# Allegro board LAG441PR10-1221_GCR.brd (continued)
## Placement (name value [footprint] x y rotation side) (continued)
CV17  0.1U_0201_10V6K  [C_0201]  43 73.42 90 top
CV18  0.1U_0201_10V6K  [C_0201]  43.57 73.42 90 top
CV19  680P_0201_50V7K  [C_0201]  34.48 75.7 0 top
CV20  0.1U_0201_10V6K  [C_0201]  36.64 76.5 180 top
CV21  10U_0402_6.3V6M  [C_0402]  37.38 74.5 180 top
CV22  22P_0201_25V8  [C_0201]  37.45 75.27 180 top
CV23  100P_0201_50V8J  [C_0201]  36.64 75.93 180 top
CV24  10U_0603_25V6M  [C_0603]  33.43 76.1 180 top
CV25  0.1U_0402_25V6  [C_0402]  33.5 77.16 180 top
CV26  0.1U_0201_10V6K  [C_0201]  60.96 62.31 0 bottom
CV27  0.1U_0201_6.3V6K  [C_0201]  304.58 4.65 180 top
CV31  10U_0402_6.3V6M  [C_0402]  47.59 57.98 90 top
CV32  0.1U_0201_10V6K  [C_0201]  46.27 58.15 90 top
CV33  0.1U_0201_10V6K  [C_0201]  45.63 58.15 90 top
CV34  68P_0201_25V8  [C_0201]  46.85 58.15 90 top
CV37  0.1U_0201_25V6K  [C_0201]  50.52 64.75 90 top
CV38  2200P_0402_50V7K  [C_0402]  52.08 64.23 90 top
CV39  0.1U_0201_10V6K  [C_0201]  70.64 61.93 0 top
CV40  0.1U_0201_25V6K  [C_0201]  60.49 62.76 0 top
CV41  2200P_0402_50V7K  [C_0402]  61.25 63.52 90 top
CV42  0.1U_0201_10V6K  [C_0201]  246.9 37.1 180 top
CV43  0.1U_0201_10V6K  [C_0201]  246.9 37.74 180 top
CV44  0.1U_0201_10V6K  [C_0201]  38.07 75.96 0 top
CV45  15P_0201_50V8J  [C_0201]  38.07 76.54 0 top
CV50  0.1U_0201_10V6K  [C_0201]  54.43 61.49 180 bottom
CV51  0.1U_0201_10V6K  [C_0201]  54.24 58.06 180 bottom
CV52  1U_0201_6.3V6M  [C_0201]  54.24 58.69 180 bottom
CV53  0.1U_0201_10V6K  [C_0201]  54.24 59.33 180 bottom
CV55  0.1U_0201_10V6K  [C_0201]  43.71 71.21 0 top
CV56  0.1U_0201_10V6K  [C_0201]  36.44 77.59 180 top
CZ1  0.1U_0201_10V6K  [C_0201]  96.9 59.45 0 bottom
CZ2  1U_0201_6.3V6M  [C_0201]  97.95 61.91 270 bottom
CZ3  1U_0201_6.3V6M  [C_0201]  80.17 63.8 0 bottom
CZ5  0.1U_0201_10V6K  [C_0201]  78.33 61.42 270 bottom
CZ6  0.1U_0201_10V6K  [C_0201]  98.53 19.07 0 bottom
CZ7  1U_0201_6.3V6M  [C_0201]  99.1 18.5 180 bottom
CZ15  0.1U_0201_10V6K  [C_0201]  43.56 29.36 0 top
CZ16  10U_0402_6.3V6M  [C_0402]  43.39 28.59 0 top
CZ17  10U_0402_6.3V6M  [C_0402]  47.08 28.59 0 top
CZ18  0.1U_0201_10V6K  [C_0201]  47.18 29.36 0 top
CZ19  0.1U_0201_10V6K  [C_0201]  44.26 36.87 90 top
CZ20  0.1U_0201_10V6K  [C_0201]  43.69 36.85 90 top
CZ21  10U_0402_6.3V6M  [C_0402]  42.9 36.98 90 top
CZ22  12P_0201_50V8J  [C_0201]  41.57 29.95 90 top
CZ23  68P_0201_50V8J  [C_0201]  41.59 29.36 0 top
CZ28  0.1U_0201_10V6K  [C_0201]  45.72 38.25 0 top
D3  -  [L05ESDL5V0NA-4_SLP2510P8-10-9]  308.09 65.88 180 top
D9  -  [BAT54LPS-7_X2-DFN1006-2-2]  201.81 33.04 0 bottom
D203  -  [RB751S40T1G_SOD523-2]  103.15 12.24 90 top
D481  -  [RB751V40_SC76-2]  146.72 21.38 180 bottom
DA1  AZ5125-01H.R7G_SOD523-2  [AZ5125-01HPR7G_SOD523-2]  292.85 28.97 0 top
DA4  AZ5123-01F.R7G_DFN1006P2X2  [AZ5123-01FPR7G_DFN1006P2X2]  298.42 14.75 0 top
DA5  AZ5123-01F.R7G_DFN1006P2X2  [AZ5123-01FPR7G_DFN1006P2X2]  295.76 26.43 270 top
DA8  AZ5123-01F.R7G_DFN1006P2X2  [AZ5123-01FPR7G_DFN1006P2X2]  306.68 25.55 270 top
DA9  AZ5123-01F.R7G_DFN1006P2X2  [AZ5123-01FPR7G_DFN1006P2X2]  304.52 25.55 270 top
DA10  -  [ESD203-B1-02EL_TSLP-2-20-2]  295.24 14.68 180 top
DA11  -  [ESD203-B1-02EL_TSLP-2-20-2]  296.62 14.68 0 top
DA12  -  [ESD203-B1-02EL_TSLP-2-20-2]  293.07 14.68 0 top
DA13  -  [ESD203-B1-02EL_TSLP-2-20-2]  291.68 14.68 180 top
DA25  AZ5123-01F.R7G_DFN1006P2X2  [AZ5123-01FPR7G_DFN1006P2X2]  299.19 16.53 180 top
DA26  AZ5123-01F.R7G_DFN1006P2X2  [AZ5123-01FPR7G_DFN1006P2X2]  299.29 13.23 180 top
DA27  -  [RB751S-40_SOD523-2]  275.67 27.64 0 top
DB3  -  [BAT54HT1G_SOD323-2]  308.2 5.67 90 top
DB4  -  [BAT54HT1G_SOD323-2]  102.7 25.01 270 top
DB5  -  [RB751S-40_SOD523-2]  313.12 2.69 180 top
DB9  -  [RB751S-40_SOD523-2]  272.26 14.43 90 top
DC1  RB751540_SOD523  [RB520SM-30T2R_EMD2-2]  128.6 31.96 0 bottom
DC2  RB751540_SOD523  [RB520SM-30T2R_EMD2-2]  118.59 30.15 270 bottom
DC5  -  [RB751S-40_SOD523-2]  110.63 59.9 0 bottom
DC6  -  [RB751S-40_SOD523-2]  110.66 61.17 0 bottom
DC7  -  [RB751S-40_SOD523-2]  123.79 31.97 90 bottom
DC8  -  [RB751S-40_SOD523-2]  37.48 77.64 0 top
DE4  -  [AZ5B25-01F_DFN0603P2Y2]  291.18 74.07 90 bottom
DE6  -  [RB751V40_SC76-2]  202.16 30.5 270 bottom
DE7  -  [RB751S-40_SOD523-2]  271.45 46.57 270 top
DE8  -  [RB751S-40_SOD523-2]  277.21 60.92 0 top
DI7  -  [AZ5B25-01F_DFN0603P2Y2]  299.44 57.64 90 top
DI8  -  [AZ5B25-01F_DFN0603P2Y2]  299.44 56.95 270 top
DI9  -  [L05ESDL5V0NA-4_SLP2510P8-10-9]  298.37 55.5 90 top
DI13  -  [AZ5B25-01F_DFN0603P2Y2]  15.04 9.6 90 bottom
DI14  -  [AZ5B25-01F_DFN0603P2Y2]  15.04 8.85 270 bottom
DI15  PESD5V0H1BSF_SOD962-2-2  [ESD101-B1-02ELS_TSSLP-2-4-2]  15.04 5.92 270 bottom
DI16  PESD5V0H1BSF_SOD962-2-2  [ESD101-B1-02ELS_TSSLP-2-4-2]  15.04 11.89 270 bottom
DI17  PESD5V0H1BSF_SOD962-2-2  [ESD101-B1-02ELS_TSSLP-2-4-2]  15.04 6.56 90 bottom
DI18  PESD5V0H1BSF_SOD962-2-2  [ESD101-B1-02ELS_TSSLP-2-4-2]  15.04 12.53 90 bottom
DM1  PESD5V0H1BSF_SOD962-2-2  [ESD101-B1-02ELS_TSSLP-2-4-2]  14.83 27.01 90 top
DM2  PESD5V0H1BSF_SOD962-2-2  [ESD101-B1-02ELS_TSSLP-2-4-2]  14.83 29.55 90 top
DM3  PESD5V0H1BSF_SOD962-2-2  [ESD101-B1-02ELS_TSSLP-2-4-2]  14.83 36.71 90 top
DM4  PESD5V0H1BSF_SOD962-2-2  [ESD101-B1-02ELS_TSSLP-2-4-2]  14.83 32.59 90 top
DM5  PESD5V0H1BSF_SOD962-2-2  [ESD101-B1-02ELS_TSSLP-2-4-2]  14.83 31.96 270 top
DM6  PESD5V0H1BSF_SOD962-2-2  [ESD101-B1-02ELS_TSSLP-2-4-2]  14.83 26.37 270 top
DM7  PESD5V0H1BSF_SOD962-2-2  [ESD101-B1-02ELS_TSSLP-2-4-2]  14.83 28.91 270 top
DM8  PESD5V0H1BSF_SOD962-2-2  [ESD101-B1-02ELS_TSSLP-2-4-2]  14.83 36.09 270 top
DN7  -  [BAT54CW_SOT323-3]  252.45 42.25 180 top
DP1  -  [AZ5B25-01F_DFN0603P2Y2]  194.92 19.2 180 bottom
DP2  -  [AZ5B25-01F_DFN0603P2Y2]  195.68 19.2 0 bottom
DP3  -  [AZ5B25-01F_DFN0603P2Y2]  193.39 19.2 0 bottom
DP4  -  [AZ5B25-01F_DFN0603P2Y2]  192.63 19.2 180 bottom
DS1  -  [L05ESDL5V0NA-4_SLP2510P8-10-9]  292.72 31.15 270 bottom
DS2  -  [PESD5V0U2BT_SOT23-3]  290.68 40.56 0 bottom
DT4  PESD5V0H1BSF_SOD962-2-2  [ESD101-B1-02ELS_TSSLP-2-4-2]  9.3 71.7 90 top
DT6  PESD5V0H1BSF_SOD962-2-2  [ESD101-B1-02ELS_TSSLP-2-4-2]  9.3 56.48 90 top
DT7  PESD5V0H1BSF_SOD962-2-2  [ESD101-B1-02ELS_TSSLP-2-4-2]  6.64 57.06 270 bottom
DT8  PESD5V0H1BSF_SOD962-2-2  [ESD101-B1-02ELS_TSSLP-2-4-2]  9.3 71.08 270 top
DT9  PESD5V0H1BSF_SOD962-2-2  [ESD101-B1-02ELS_TSSLP-2-4-2]  6.64 70.89 90 bottom
DT10  PESD5V0H1BSF_SOD962-2-2  [ESD101-B1-02ELS_TSSLP-2-4-2]  9.3 55.86 270 top
DT11  PESD5V0H1BSF_SOD962-2-2  [ESD101-B1-02ELS_TSSLP-2-4-2]  6.64 55.67 90 bottom
DT12  -  [AZ5B25-01F_DFN0603P2Y2]  10.09 70.51 0 top
DT13  -  [AZ5B25-01F_DFN0603P2Y2]  5.55 70.62 0 bottom
DT14  -  [AZ5B25-01F_DFN0603P2Y2]  10.09 55.29 0 top
DT15  -  [AZ5B25-01F_DFN0603P2Y2]  5.55 55.4 0 bottom
DT16  -  [AZ5B25-01F_DFN0603P2Y2]  9.3 69.78 0 top
DT17  -  [AZ5B25-01F_DFN0603P2Y2]  5.55 69.14 0 bottom
DT18  -  [AZ5B25-01F_DFN0603P2Y2]  9.3 54.56 0 top
DT19  -  [AZ5B25-01F_DFN0603P2Y2]  5.55 54.66 0 bottom
DT20  -  [AZ5B25-01F_DFN0603P2Y2]  9.3 68.9 0 top
DT21  -  [AZ5B25-01F_DFN0603P2Y2]  5.55 69.88 0 bottom
DT22  -  [AZ5B25-01F_DFN0603P2Y2]  9.3 53.68 0 top
DT23  -  [AZ5B25-01F_DFN0603P2Y2]  5.55 53.92 0 bottom
DT24  -  [AZ5B25-01F_DFN0603P2Y2]  10.09 68.17 0 top
DT25  -  [AZ5B25-01F_DFN0603P2Y2]  5.55 68.41 0 bottom
DT26  -  [AZ5B25-01F_DFN0603P2Y2]  10.09 52.95 0 top
DT27  -  [AZ5B25-01F_DFN0603P2Y2]  5.55 53.19 0 bottom
DT28  PESD5V0H1BSF_SOD962-2-2  [ESD101-B1-02ELS_TSSLP-2-4-2]  9.3 67.59 90 top
DT29  PESD5V0H1BSF_SOD962-2-2  [ESD101-B1-02ELS_TSSLP-2-4-2]  6.64 68.14 270 bottom
DT30  PESD5V0H1BSF_SOD962-2-2  [ESD101-B1-02ELS_TSSLP-2-4-2]  9.3 52.37 90 top
DT31  PESD5V0H1BSF_SOD962-2-2  [ESD101-B1-02ELS_TSSLP-2-4-2]  6.64 52.92 270 bottom
DT32  PESD5V0H1BSF_SOD962-2-2  [ESD101-B1-02ELS_TSSLP-2-4-2]  9.3 66.97 270 top
DT33  PESD5V0H1BSF_SOD962-2-2  [ESD101-B1-02ELS_TSSLP-2-4-2]  6.64 66.76 90 bottom
DT34  PESD5V0H1BSF_SOD962-2-2  [ESD101-B1-02ELS_TSSLP-2-4-2]  9.3 51.75 270 top
DT35  PESD5V0H1BSF_SOD962-2-2  [ESD101-B1-02ELS_TSSLP-2-4-2]  6.64 51.54 90 bottom
DT42  PESD5V0H1BSF_SOD962-2-2  [ESD101-B1-02ELS_TSSLP-2-4-2]  6.64 72.28 270 bottom
DT43  BAT54LPS-7  [BZT52C15LP-7_DFN1006-2-2]  20.23 67.18 0 bottom
DT44  AZ4024-02S_SOT23-3~D  [PESD24VS2UT_SOT23-3]  20.38 69.86 180 top
DT45  BAT54LPS-7  [BZT52C15LP-7_DFN1006-2-2]  20.13 74.09 0 bottom
DT46  AZ4024-02S_SOT23-3~D  [PESD24VS2UT_SOT23-3]  21.02 73.36 90 top
DT47  -  [RB520SM-30T2R_EMD2-2]  17.18 66.65 270 bottom
DT48  -  [RB520SM-30T2R_EMD2-2]  14.52 66.65 270 bottom
DT49  -  [RB520SM-30T2R_EMD2-2]  15.91 66.65 270 bottom
DV1  -  [BAT54CW_SOT323-3]  45.29 68.39 180 top
DV2  -  [BAT54CW_SOT323-3]  43.94 66.77 270 top
DV3  -  [BAT54CW_SOT323-3]  37.1 71.63 0 top
DV4  -  [AZ5B25-01F_DFN0603P2Y2]  117.65 21.01 90 bottom
DV5  -  [AZ5B25-01F_DFN0603P2Y2]  117.65 20.32 270 bottom
DV6  -  [AZ5B25-01F_DFN0603P2Y2]  139.61 18.9 0 bottom
DV7  -  [AZ5B25-01F_DFN0603P2Y2]  138.92 18.9 180 bottom
DV10  -  [AZ5B25-01F_DFN0603P2Y2]  52.74 60.78 90 bottom
DV11  -  [AZ5B25-01F_DFN0603P2Y2]  52.74 60.04 270 bottom
DV12  -  [BAT54LPS-7_X2-DFN1006-2-2]  134.2 16.49 270 bottom
DV13  -  [RB751S-40_SOD523-2]  51.87 62.64 180 top
DV14  -  [RB751S-40_SOD523-2]  62.1 61.8 180 top
FD1  FIDUCAL  [FIDUCIAL_C40M80]  296.77 75.2 0 top
FD2  FIDUCIAL  [FIDUCIAL_C40M80]  16.93 2.94 0 top
FD3  FIDUCAL  [FIDUCIAL_C40M80]  286.55 66 180 bottom
FD4  FIDUCIAL  [FIDUCIAL_C40M80]  27.85 3.07 180 bottom
FK1  0.5A_6V_0402L050SLKR  [F_0402L050SLKR]  211.94 17.43 90 top
H1  -  [H_3P8N]  55.98 54.59 0 top
H2  -  [H_3P8N]  119.31 67.43 0 top
H3  -  [H_3P8N]  55.98 37.03 0 top
H4  -  [H_3P8N]  119.31 36.93 0 top
H5  -  [H_4P2]  266.89 69.74 0 top
H6  -  [H_4P2]  243.88 31.04 0 top
H7  -  [CLIP_C6-NPM]  194.3 66.76 180 bottom
H8  -  [CLIP_C6-NPM]  137.78 31.14 180 bottom
H9  -  [H_4P2]  288.82 55.36 0 top
H10  -  [H_4P2]  301.88 70.24 0 top
H30  -  [H_2P3]  298.57 48.91 0 top
H31  -  [H_2P3]  2.98 78.11 0 top
H32  -  [H_2P3]  2.98 45.03 0 top
H33  -  [H_2P3]  11.88 20.2 0 top
H34  -  [H_2P3]  244.08 75.25 0 top
H35  -  [H_2P3]  204.43 22.91 0 top
H36  -  [H_3P2]  92.88 76.01 0 top
H37  -  [H_3P2]  217.88 76.01 0 top
H38  -  [H_2P3]  286.98 76.01 0 top
H39  -  [H_2P3]  298.58 21.61 0 top
H63  -  [H_1P1X1P5N]  115.97 12.66 90 top
H64  -  [H_1P1N]  119.58 12.66 0 top
H65  -  [H_1P1N]  204.43 16.31 0 top
H66  -  [H_1P1X1P5N]  204.43 12.71 0 top
H72  -  [H_4P2N]  238.82 55.36 0 top
H73  -  [H_1P8X2P2N]  7.32 20.74 90 top
H75  -  [H_1P8N]  298.58 44.11 0 top
H76  -  [H_1P3N]  5.98 61.53 0 top
H77  -  [H_1P3X1P8N]  5.98 46.73 0 top
H78  -  [H_1P3N]  242.43 55.37 0 top
JANT1  BELLW_10093-1021  [BELLW_10093-1021_4P]  211.98 70.12 180 bottom
JANT2  BELLW_10093-1021  [BELLW_10093-1021_4P]  193.67 72.09 180 bottom
JAPS1  ACES_50506-01841-P01  [ACES_50506-01841-P01_18P]  128.79 33.61 90 top
JBATT1  DEREN_40-42507-01001RHF_10P  [DEREN_40-42507-01001RHF_10P-T]  37.72 12.89 90 bottom
JBL1  ACES_51575-00401-001  [ACES_51575-00401-001_4P]  216.96 17.84 180 bottom
JCAM1  I-PEX_20599-021E-01  [I-PEX_20599-021E-01_21P-T]  131.35 20.14 90 bottom
JCR1  T-SOL_158-1160902600  [T-SOL_158-1160902600_23P-T]  301.2 36.56 90 top
JDEG1  -  [ACES_50521-01041-P01_10P]  237.13 72.14 180 bottom
JEDP1  I-PEX_20879-040E-01  [I-PEX_20879-040E-01_40P-T]  32.03 77.81 180 bottom
JESPI1  -  [ACES_50521-01041-P01_10P]  229.13 72.14 180 bottom
JFAN1  ACES_50224-00401-001  [ACES_50224-00401-001_4P]  198.85 28.64 90 bottom
JFP1  FOX_QT510166-L010-7H  [FOX_QT510166-L010-7H_16P]  312.01 67.82 90 bottom
JHDMI1  LOTES_AHDM0056-P002A  [LOTES_AHDM0056-P001A_19P]  11.25 27.23 90 bottom
JHP1  SINGA_2SJ3095-052111F  [SINGA_2SJ3095-052111F_6P-T]  303.25 22.02 90 bottom
JKB1  JXT_FP257H-032S10M  [JXT_FP257H-032S10M_32P]  249.33 17.91 180 bottom
JLED1  ELCO_046809604110846+  [ELCO_46809604110846_4P-T]  137.17 16.51 180 bottom
JLTE1  I-PEX_20854-005E-00  [I-PEX_20854-005E-00_5P-T]  207.28 72.32 180 bottom
JLTE2  I-PEX_20854-005E-00  [I-PEX_20854-005E-00_5P-T]  199.78 72.32 180 bottom
JNGFF1  LOTES_APCI0144-P007A  [LOTES_APCI0144-P007A_75P]  257.65 24.06 0 bottom
JNGFF2  LOTES_APCI0146-P004A  [LOTES_APCI0146-P004A_75P]  205.3 64.61 270 bottom
JNGFF3  LOTES_APCI0147-P007A  [LOTES_APCI0147-P007A_75P]  210.2 40.3 270 bottom
JPTN1  ELCO_046809604110846+  [ELCO_46809604110846_4P-T]  293.46 73.79 270 bottom
JRTC1  ACES_50278-00201-001  [ACES_50278-00201-001_2P]  307.05 1.4 0 bottom
JSIM1  JAE_SF51S006V4DR1000Q  [JAE_SF51S006V4DR1000Q_8P]  299.33 38.33 270 bottom
JSPI1  -  [ACES_50521-01041-P01_10P]  108.27 11.68 180 bottom
JSPK1  ACES_50208-00601-P01  [ACES_50208-00601-P01_6P]  293.37 16.51 180 bottom
JTP1  STARC_106A08-001020-A2-R  [STARC_106A08-001020-A2-R_8P-T]  191.12 17.41 180 bottom
JUSB1  SANTA_375230-1  [SANTA_375230-1_9P]  304.06 48.61 270 bottom
JUSB2  SANTA_375230-1  [SANTA_375230-1_9P]  11.71 12.74 90 bottom
JUSBC1  JAE_DX07SD24JJ2R1300~D  [JAE_DX07SD24JJ2R1300_24P]  7.65 56.87 270 top
JUSBC2  JAE_DX07SD24JJ2R1300~D  [JAE_DX07SD24JJ2R1300_24P]  7.65 72.08 270 top
JUSH1  CVILU_CF5026FD0RK-05-NH  [CVILU_CF5026FD0RK-05-NH_26P-T]  278.06 18.84 180 bottom
JXDP1  JXT_FP270H-061G1AM  [JXT_FP270H-061G1AM_61P]  69.58 72.26 180 top
L2  DLM0NSN900HY2D_4P  [MURAT_DLM0NSN900HY2D_4P]  308.08 63.16 90 top
L3  BLM15AG121SN1D_L0402_2P  [MURAT_BLM15AG121SN1D_L0402_2P]  109.97 51.96 0 top
LA1  HCB2012KF-600T30  [MURAT_BLM21PG600SN1D_2P]  289.91 29.42 0 top
LA2  HCB1608KF-121T30_0603  [CHILI_PBY160808T-300Y-N_2P]  285.96 32.46 225 bottom
LA3  BLM15PX330SN1D_2P  [MURAT_BLM15PX330SN1D_2P]  293.09 23.77 0 top
LA4  BLM15PX330SN1D_2P  [MURAT_BLM15PX330SN1D_2P]  293.09 19.39 0 top
LA5  BLM15PX330SN1D_2P  [MURAT_BLM15PX330SN1D_2P]  292.71 22.75 0 top
LA6  BLM15PX330SN1D_2P  [MURAT_BLM15PX330SN1D_2P]  292.71 21.35 0 top
LA7  BLM15PX121SN1D_2P  [MURAT_BLM15PX121SN1D_2P]  294.91 12.4 90 top
LA8  BLM15PX121SN1D_2P  [MURAT_BLM15PX121SN1D_2P]  296.95 12.4 90 top
LA9  BLM15PX121SN1D_2P  [MURAT_BLM15PX121SN1D_2P]  293.39 12.4 90 top
LA10  BLM15PX121SN1D_2P  [MURAT_BLM15PX121SN1D_2P]  291.36 12.4 90 top
LB1  DLM0NSN900HY2D_4P  [MURAT_DLM0NSN900HY2D_4P]  274.38 17.87 270 top
LC1  CPI160809UF_2P  [MURAT_BLM18EG221TN1D_2P]  102.3 60.76 270 bottom
LC2  CPI160809UF_2P  [MURAT_BLM18EG221TN1D_2P]  113.07 56.36 0 bottom
LC3  BLM18EG221TN1D_2P  [MURAT_BLM18EG221TN1D_2P]  98.34 50.54 270 top
LED1  HT-F196BP5_WHITE  [LED_HT-F196BP5_2P]  197.92 62.57 0 bottom
LED_PRI  HT-F196BP5_WHITE  [LED_HT-F196BP5_2P]  116.8 54.41 270 bottom
LED_RST  HT-F196BP5_WHITE  [LED_HT-F196BP5_2P]  197.92 60.19 0 bottom
LED_RUN  HT-F196BP5_WHITE  [LED_HT-F196BP5_2P]  197.92 58.98 0 bottom
LI1  DLM0NSN900HY2D_4P  [MURAT_DLM0NSN900HY2D_4P]  297.81 57.55 0 top
LI4  DLM0NSN900HY2D_4P  [MURAT_DLM0NSN900HY2D_4P]  16.54 9.48 180 bottom
LN4  DLM0NSN900HY2D_4P  [MURAT_DLM0NSN900HY2D_4P]  259.68 26.8 270 top
LN6  DLM0NSN900HY2D_4P  [MURAT_DLM0NSN900HY2D_4P]  207.06 39.27 0 bottom
LN9  BLM15AG121SN1D_L0402_2P  [MURAT_BLM15AG121SN1D_L0402_2P]  199.24 69.77 90 top
LN10  BLM15AG121SN1D_L0402_2P  [MURAT_BLM15AG121SN1D_L0402_2P]  200.38 69.77 90 top
LN11  BLM15AG121SN1D_L0402_2P  [MURAT_BLM15AG121SN1D_L0402_2P]  193.31 69.42 0 top
LN12  1.8NH +-0.1NH LQP03TN1N8B02D  [MURAT_LQP03TN1N8B00D_2P]  202.39 72.46 180 bottom
LN13  1.8NH +-0.1NH LQP03TN1N8B02D  [MURAT_LQP03TN1N8B00D_2P]  196.58 72.92 90 bottom
LN14  3.3NH_LQP03TN3N3B02D_0.1NH  [MURAT_LQP03TN3N3B00D_2P]  203.09 72.46 0 bottom
LN15  0_0201_5%  [R0201_0OHM]  196.63 72.2 270 bottom
LS3  150NH_BSCH00100505R15JCS_5%  [MURAT_LQG15HSR15J02D_2P]  202.61 71.56 270 bottom
LS4  150NH_BSCH00100505R15JCS_5%  [MURAT_LQG15HSR15J02D_2P]  208.27 70.73 180 bottom
LS5  150NH_BSCH00100505R15JCS_5%  [MURAT_LQG15HSR15J02D_2P]  202.07 68.27 180 top
LS6  150NH_BSCH00100505R15JCS_5%  [MURAT_LQG15HSR15J02D_2P]  197.45 67.68 0 top
LT1  0.6UH_MND-04ABIR60M-XGL_20%  [MAG_MND-04ABIR60M-XGL_2P]  19.95 60.41 180 bottom
LT2  1UH_LQM18PN1R0MFHD_20%  [CHILI_PBY160808T-300Y-N_2P]  18.38 53.74 90 top
LT3  0_0805_5%  [R_0805]  20.73 65.75 180 bottom
LT4  0_0805_5%  [R_0805]  20.67 72.61 180 bottom
LT9  DLM0NSN900HY2D_4P  [MURAT_DLM0NSN900HY2D_4P]  11.17 53.87 180 top
LT10  DLM0NSN900HY2D_4P  [MURAT_DLM0NSN900HY2D_4P]  11.17 69.08 180 top
LT11  DLM0NSN900HY2D_4P  [MURAT_DLM0NSN900HY2D_4P]  7.39 54.54 180 bottom
LT12  DLM0NSN900HY2D_4P  [MURAT_DLM0NSN900HY2D_4P]  7.39 69.76 180 bottom
LV6  DLM0NSN900HY2D_4P  [MURAT_DLM0NSN900HY2D_4P]  54.19 60.66 180 bottom
NOREF  -  []  249.17 18.8 0 top
NOREF#2  -  []  104.66 -31.71 0 top
NOREF#3  -  []  209.24 70.17 0 top
NOREF#4  -  []  174.14 -9.7 0 top
NOREF#5  -  []  254.43 13.53 0 top
NOREF#6  -  []  224 28.07 0 top
NOREF#7  -  []  229.75 29.85 0 top
NOREF#8  -  []  69.57 10.24 180 bottom
NOREF#9  -  []  266.23 58.82 180 bottom
NOREF#10  -  []  276.9 56.79 180 bottom
NOREF#11  -  []  256.58 49.17 180 bottom
NOREF#12  -  []  182.79 22.43 180 bottom
PC100  2200P_0402_50V7K  [C_0402]  8.86 67.96 180 bottom
PC101  0.01U_0402_25V7K  [C_0402]  8.88 66.95 180 bottom
PC102  0.1U_0402_25V6  [C_0402]  8.17 75.38 90 bottom
PC103  100P_0201_25V7K  [C_0201]  10.49 65.33 90 bottom
PC104  2200P_0402_50V7K  [C_0402]  9.38 60.34 180 bottom
PC105  1000P_0201_50V7K  [C_0201]  12.36 64.62 90 bottom
PC106  100P_0201_25V7K  [C_0201]  11.72 64.62 90 bottom
PC107  0.1U_0402_25V6  [C_0402]  13.12 64.2 90 bottom
PC108  1U_0603_25V6K  [C_0603]  10.01 62.76 180 bottom
PC109  10U_0603_25V6M  [C_0603]  10.01 61.49 180 bottom
PC110  0.47U_0402_25V6K  [C_0402]  14.32 67.93 180 top
PC111  680P_0402_50V7K  [C_0402]  11.47 63.33 270 top
PC112  1000P_0402_50V7K  [C_0402]  37.31 61.8 0 top
PC113  2200P_0402_50V7K  [C_0402]  9.73 54.61 0 bottom
PC114  0.01U_0402_25V7K  [C_0402]  9.74 53.61 0 bottom
PC115  0.1U_0402_25V6  [C_0402]  8.62 52.98 180 bottom
PC116  100P_0201_25V7K  [C_0201]  9.96 52.83 0 bottom
PC117  2200P_0402_50V7K  [C_0402]  12.86 51.25 90 bottom
PC118  1000P_0201_50V7K  [C_0201]  10.58 51.16 90 bottom
PC119  100P_0201_25V7K  [C_0201]  11.21 51.16 90 bottom
PC120  0.1U_0402_25V6  [C_0402]  11.98 51.25 90 bottom
PC121  1U_0603_25V6K  [C_0603]  10.08 46.77 180 bottom
PC122  10U_0603_25V6M  [C_0603]  10.08 47.97 180 bottom
PC123  0.47U_0402_25V6K  [C_0402]  11.47 51.36 270 top
PC124  680P_0402_50V7K  [C_0402]  13.38 40.29 0 top
PC130  0.01U_0402_50V7K  [C_0402]  18.58 44.55 90 top
PC131  0.01U_0402_50V7K  [C_0402]  17.69 44.55 90 top
PC132  0.01UF_0402_25V7K  [C_0402]  45.64 21.25 90 bottom
PC133  100P_0201_50V8J  [C_0201]  45.47 20.5 270 bottom
PC134  1000P_0201_50V7K  [C_0201]  42.31 13.18 270 top
PC135  100P_0201_50V8J  [C_0201]  41.52 13.18 270 top
PC136  2.2U_0402_25V6M  [C_0402]  16.03 43.44 0 top
PC137  10U_0402_6.3V6M  [C_0402]  19.6 41.81 270 top
PC138  100P_0402_50V8J  [C_0402]  22.03 42.64 90 top
PC139  0.1U_0402_10V7K  [C_0402]  15.19 40.85 90 top
PC140  10U_0402_6.3V6M  [C_0402]  24.66 45.74 90 top
PC141  100P_0402_50V8J  [C_0402]  20.23 45.46 270 top
PC142  2.2U_0402_25V6M  [C_0402]  23.68 42.64 90 top
PC143  0.1U_0402_10V7K  [C_0402]  26.1 42.97 270 top
PC200  0.1U_0402_25V6  [C_0402]  22.39 41.56 270 bottom
PC201  0.1U_0402_25V6  [C_0402]  17.56 36.56 180 bottom
PC202  2200P_0402_50V7K  [C_0402]  19.11 40.67 0 bottom
PC203  10U_0603_25V6M  [C_0603]  20.99 36.72 0 top
PC204  10U_0603_25V6M  [C_0603]  18.07 37.61 180 bottom
PC205  10U_0603_25V6M  [C_0603]  18.07 38.8 180 top
PC206  10U_0603_25V6M  [C_0603]  20.99 36.72 0 bottom
PC207  10U_0603_25V6M  [C_0603]  18.07 40 180 bottom
PC208  10U_0603_25V6M  [C_0603]  18.07 38.8 180 bottom
PC209  10U_0603_25V6M  [C_0603]  18.07 40 180 top
PC210  4.7U_0603_25V6K  [C_0603]  26.67 21.66 0 top
PC211  0.1U_0402_25V6  [C_0402]  21.49 42.44 0 bottom
PC212  1U_0402_25V6K  [C_0402]  25.37 22.78 90 top
PC213  1U_0402_25V6K  [C_0402]  28.04 22.78 90 top
PC214  10U_0603_25V6M  [C_0603]  294.11 55.58 90 bottom
PC215  10U_0603_25V6M  [C_0603]  43.36 30.67 180 bottom
PC216  10U_0603_25V6M  [C_0603]  43.26 28.24 180 bottom
PC217  10U_0603_25V6M  [C_0603]  43.27 27.01 180 bottom
PC218  33U_B2_20VM_R90M  [C_B2]  46.62 36.68 180 bottom
PC219  33U_B2_20VM_R90M  [C_B2]  46.62 33.44 180 bottom
PC221  10U_0603_25V6M  [C_0603]  43.36 29.45 180 bottom
PC222  10U_0603_25V6M  [C_0603]  42.13 33.16 270 bottom
PC223  0.1U_0402_25V6  [C_0402]  41.09 37.39 180 bottom
PC224  2200P_0402_50V7K  [C_0402]  294.99 52.29 270 bottom
PC225  0.22U_0603_25V7K  [C_0603]  31.53 22.5 270 top
PC226  1U_0402_25V6K  [C_0402]  24.09 21.33 0 top
PC227  1U_0402_25V6K  [C_0402]  23.21 20.45 90 top
PC228  2.2U_0402_6.3V6M  [C_0402]  33.31 20.64 90 top
PC229  2.2U_0402_6.3V6M  [C_0402]  23.65 19.58 0 top
PC230  0.22U_0603_25V7K  [C_0603]  33.5 18.31 0 top
PC231  10U_0603_25V6M  [C_0603]  43.29 25.77 180 bottom
PC232  10U_0603_25V6M  [C_0603]  43.27 24.53 180 bottom
PC233  4700P_0402_25V7K  [C_0402]  44.37 23.02 270 top
PC234  2200P_0402_50V7K  [C_0402]  33.91 13.72 0 top
PC235  0.1U_0402_25V6  [C_0402]  33.04 17.19 270 top
PC236  680P_0402_50V7K  [C_0402]  26.29 28.7 90 top
PC237  680P_0402_50V7K  [C_0402]  32.73 29.61 270 top
PC238  1U_0402_25V6K  [C_0402]  34.82 15.5 180 top
PC239  1U_0402_25V6K  [C_0402]  33.04 15.45 270 top
PC240  1U_0402_25V6K  [C_0402]  33.91 14.61 0 top
PC241  560P_0402_50V7K  [C_0402]  27.78 13.85 270 top
PC243  0.01U_0402_16V7K  [C_0402]  26.77 12.07 270 top
PC244  0.1U_0402_25V6  [C_0402]  28.62 11.99 180 top
PC245  0.1U_0402_25V6  [C_0402]  30.7 13.82 270 top
PC300  33U_B2_20VM_R90M  [C_B2]  198.72 37.41 0 bottom
PC301  0.1U_0402_25V6  [C_0402]  198.87 45.98 0 bottom
PC302  2200P_0402_50V7K  [C_0402]  198.36 39.52 180 bottom
PC303  10U_0603_25V6M  [C_0603]  200.81 38.09 0 bottom
PC304  10U_0603_25V6M  [C_0603]  200.81 39.34 0 bottom
PC305  0.22U_0402_25V6K  [C_0402]  198.84 46.88 0 bottom
PC306  47U_0603_6.3V6M  [C_0603]  193.71 41.93 0 bottom
PC307  47U_0603_6.3V6M  [C_0603]  193.71 45.55 0 bottom
PC308  47U_0603_6.3V6M  [C_0603]  193.71 44.34 0 bottom
PC309  0.1U_0201_6.3V6K  [C_0201]  200.06 42.98 270 top
PC310  150P_0402_50V8J  [C_0402]  203.01 41.22 90 bottom
PC311  47U_0603_6.3V6M  [C_0603]  193.71 40.72 0 bottom
PC312  47U_0603_6.3V6M  [C_0603]  193.71 43.14 0 bottom
PC313  1U_0402_16V6K  [C_0402]  196.96 45.99 180 bottom
PC314  680P_0402_50V7K  [C_0402]  200.94 55.94 270 bottom
PC400  0.22U_0402_25V6K  [C_0402]  39.03 40.44 90 top
PC401  0.1U_0402_25V6  [C_0402]  44.09 40.82 270 bottom
PC402  2200P_0402_50V7K  [C_0402]  46.53 41.72 90 bottom
PC403  10U_0603_16VAM  [C_0603]  44.25 41.77 90 bottom
PC404  10U_0603_16VAM  [C_0603]  45.47 41.77 90 bottom
PC405  4.7U_0402_6.3V6M  [C_0402]  40.75 39.48 270 top
PC406  22U_0603_6.3V6M  [C_0603]  32.25 43.39 90 bottom
PC407  22U_0603_6.3V6M  [C_0603]  32.31 41.87 270 bottom
PC408  22U_0603_6.3V6M  [C_0603]  30.58 45.88 0 bottom
PC409  22U_0603_6.3V6M  [C_0603]  33.54 41.85 270 bottom
PC410  22U_0603_6.3V6M  [C_0603]  30.34 39.28 0 bottom
PC411  1U_0402_16V6K  [C_0402]  40.17 43.36 0 bottom
PC412  680P_0402_50V7K  [C_0402]  35.34 39.27 180 top
PC413  0.22U_0402_25V6K  [C_0402]  298.75 65.04 180 top
PC414  0.1U_0402_25V6  [C_0402]  298.35 56.28 0 bottom
PC415  2200P_0402_50V7K  [C_0402]  298.35 57.17 0 bottom
PC416  10U_0603_25V6M  [C_0603]  298.36 55.2 0 bottom
PC417  10U_0603_25V6M  [C_0603]  297.34 56.91 180 bottom
PC418  4.7U_0402_6.3V6M  [C_0402]  293.98 61.18 270 bottom
PC419  22U_0603_6.3V6M  [C_0603]  291.98 62.97 180 bottom
PC420  22U_0603_6.3V6M  [C_0603]  295.96 67.76 90 bottom
PC421  22U_0603_6.3V6M  [C_0603]  291.98 66.61 180 bottom
PC422  22U_0603_6.3V6M  [C_0603]  291.98 65.42 180 bottom
PC423  22U_0603_6.3V6M  [C_0603]  291.98 64.19 180 bottom
PC424  1U_0402_16V6K  [C_0402]  299.97 61.55 270 bottom
PC425  680P_0402_50V7K  [C_0402]  296.9 64.99 270 top
PC426  22U_0603_6.3V6M  [C_0603]  33.48 43.38 90 bottom
PC500  0.22U_0402_25V6K  [C_0402]  111.15 20.67 90 bottom
PC501  10U_0603_25V6M  [C_0603]  116.97 24.24 90 bottom
PC502  10U_0603_25V6M  [C_0603]  118.75 23.14 270 bottom
PC503  0.1U_0402_25V6  [C_0402]  116.81 23.18 270 bottom
PC504  2200P_0402_25V7K  [C_0402]  117.7 23.19 270 bottom
PC505  220P_0201_25V7K  [C_0201]  113.6 27 0 bottom
PC506  22U_0603_6.3V6M  [C_0603]  110.58 28.25 180 bottom
PC507  22U_0603_6.3V6M  [C_0603]  110.57 29.51 180 bottom
PC508  22U_0603_6.3V6M  [C_0603]  113.11 27.89 0 bottom
PC509  22U_0603_6.3V6M  [C_0603]  113.12 29.11 0 bottom
PC510  2.2U_0201_6.3V6M  [C_0201]  113.72 25.45 0 bottom
PC512  680P_0402_50V7K  [C_0402]  107.53 21.52 90 bottom
PC600  10U_0603_25V6M  [C_0603]  49.25 28.25 0 bottom
PC601  10U_0603_25V6M  [C_0603]  49.25 29.48 0 bottom
PC602  0.1U_0402_25V6  [C_0402]  49.24 28.09 0 top
PC603  2200P_0402_25V7K  [C_0402]  49.24 28.97 0 top
PC604  680P_0402_50V7K  [C_0402]  49.46 21.43 90 top
PC605  .1U_0402_16V7K  [C_0402]  46.49 21.44 0 top
PC606  2.2U_0402_6.3V6M  [C_0402]  47.06 23.82 0 top
PC607  4.7U_0402_6.3V6M  [C_0402]  46.61 23.74 270 bottom
PC608  22U_0603_6.3V6M  [C_0603]  52.11 23.78 0 bottom
PC609  330P_0402_50V7K  [C_0402]  50.64 23.41 180 top
PC610  22U_0603_6.3V6M  [C_0603]  52.13 22.58 0 bottom
PC611  22U_0603_6.3V6M  [C_0603]  52.49 16.14 270 bottom
PC612  22U_0603_6.3V6M  [C_0603]  53.7 16.15 270 bottom
PC613  22U_0603_6.3V6M  [C_0603]  51.73 17.63 180 top
PC614  2.2U_0402_6.3V6M  [C_0402]  50.54 26 270 top
PC615  22U_0603_6.3V6M  [C_0603]  52.11 25 0 bottom
PC616  22U_0603_6.3V6M  [C_0603]  51.72 18.88 180 top
PC619  22U_0603_6.3V6M  [C_0603]  51.74 20.12 180 top
PC620  10U_0603_25V6M  [C_0603]  48.16 28.25 180 bottom
PC700  4.7U_0402_6.3V6M  [C_0402]  123.41 42.01 0 bottom
PC800  680P_0603_50V7K  [C_0603]  123.16 58.82 0 top
PC801  2200P_0402_50V7K  [C_0402]  124.76 53.38 270 bottom
PC802  10U_0603_25V6M  [C_0603]  125.87 52.79 270 bottom
PC803  0.1U_0201_10VX7SK  [C_0201]  125.52 56.72 180 bottom
PC804  0.1U_0402_25V6  [C_0402]  124.76 54.25 90 bottom
PC805  10U_0603_16VAM  [C_0603]  125.85 53.75 90 bottom
PC806  330P_0402_50V7K  [C_0402]  117.99 55.31 0 bottom
PC807  22U_0603_6.3V6M  [C_0603]  124.33 62.58 90 bottom
PC808  22U_0603_6.3V6M  [C_0603]  121.89 62.58 90 bottom
PC809  22U_0603_6.3V6M  [C_0603]  120.17 60.84 90 bottom
PC810  22U_0603_6.3V6M  [C_0603]  123.11 62.58 90 bottom
PC811  4.7U_0402_6.3V6M  [C_0402]  120.38 57.11 180 bottom
PC813  2.2U_0402_6.3V6M  [C_0402]  118.91 56.22 180 bottom
PC900  0.01U_0402_50V7K  [C_0402]  39.12 60.43 90 top
PC901  1U_0603_10V6K  [C_0603]  45.44 54.12 180 bottom
PC902  4.7U_0402_10V6M  [C_0402]  40.78 58.67 270 bottom
PC903  0.1U_0402_25V6  [C_0402]  48.93 51.26 315 top
PC904  150P_0402_50V8J  [C_0402]  45.39 63.65 0 top
PC905  1U_0402_10V6K  [C_0402]  40.87 58.75 90 top
PC906  0.01U_0402_16V7K  [C_0402]  45.44 65.5 270 top
PC907  150P_0402_50V8J  [C_0402]  47.14 63.65 0 top
PC908  0.01U_0402_16V7K  [C_0402]  47.22 65.5 270 top
PC909  390P_0402_50V7K  [C_0402]  51.07 59.47 180 bottom
PC910  150P_0402_50V8J  [C_0402]  51.08 58.58 180 bottom
PC911  33P_0402_50V8J  [C_0402]  51.03 56.86 180 bottom
PC912  150P_0402_50V8J  [C_0402]  50.86 61.16 0 bottom
PC913  1U_0603_10V6K  [C_0603]  40.76 59.68 90 bottom
PC914  0.01U_0402_16V7K  [C_0402]  49 64.59 90 top
PC1000  0.1U_0402_25V7K  [C_0402]  72.87 73.23 270 top
PC1001  2200P_0402_50V7K  [C_0402]  73.89 73.23 270 top
PC1002  10U_0603_16VAM  [C_0603]  70.5 72.83 270 bottom
PC1003  10U_0603_16VAM  [C_0603]  71.7 72.83 270 bottom
PC1004  1U_0402_16VAK  [C_0402]  77.19 74 90 bottom
PC1005  1U_0402_16VAK  [C_0402]  75.79 76 180 bottom
PC1006  0.22U_0402_25VAK  [C_0402]  77.44 75.9 0 bottom
PC1007  680P_0402_50V7K  [C_0402]  80.27 70.98 0 top
PC1008  33U_B2_20VM_R90M  [C_B2]  68.11 71.72 0 bottom
PC1010  33U_B2_20VM_R90M  [C_B2]  117.55 72.76 270 bottom
PC1011  33U_B2_20VM_R90M  [C_B2]  120.81 72.73 270 bottom
PC1013  100U_D2_20VM_R55M  [C_D2]  66.71 67.73 0 bottom
PC1015  0.1U_0402_25V7K  [C_0402]  111.92 72.41 90 top
PC1016  2200P_0402_50V7K  [C_0402]  112.81 72.41 90 top
PC1017  10U_0603_16VAM  [C_0603]  115.28 71.46 270 bottom
PC1018  10U_0603_16VAM  [C_0603]  114.02 72.47 90 bottom
PC1019  1U_0402_16VAK  [C_0402]  108.5 71.63 270 bottom
PC1020  1U_0402_16VAK  [C_0402]  109.8 69.63 0 bottom
PC1021  0.22U_0402_25VAK  [C_0402]  108.51 69.84 180 bottom
PC1022  680P_0402_50V7K  [C_0402]  103.2 69.65 180 top
PC1100  0.1U_0402_25V7K  [C_0402]  39.36 50.3 90 bottom
PC1101  2200P_0402_50V7K  [C_0402]  40.29 50.29 90 bottom
PC1102  10U_0603_16VAM  [C_0603]  38.95 49.33 270 bottom
PC1103  10U_0603_16VAM  [C_0603]  40.15 49.32 270 bottom
PC1104  1U_0402_16VAK  [C_0402]  45.79 49.89 90 bottom
PC1105  1U_0402_16VAK  [C_0402]  44.36 52.08 180 bottom
PC1106  0.22U_0402_25VAK  [C_0402]  45.87 51.71 0 bottom
PC1107  680P_0402_50V7K  [C_0402]  46 45.71 0 top
PC1108  0.1U_0402_25V6  [C_0402]  128.59 67.32 180 top
PC1109  2200P_0402_50V7K  [C_0402]  128.59 68.23 180 top
PC1110  10U_0603_25V6M  [C_0603]  128.97 70.94 180 bottom
PC1111  10U_0603_25V6M  [C_0603]  129.96 69.7 0 bottom
PC1112  10U_0603_25V6M  [C_0603]  128.96 69.69 180 bottom
PC1113  1U_0402_16VAK  [C_0402]  129.31 64.21 0 bottom
PC1114  1U_0402_25V6K  [C_0402]  131.12 66.03 90 bottom
PC1115  0.22U_0603_25V7K  [C_0603]  131.25 65.14 270 bottom
PC1116  680P_0402_50V7K  [C_0402]  126.49 61.96 270 top
PC1117  33U_B2_20VM_R90M  [C_B2]  36.9 50.56 0 bottom
PC1118  33U_B2_20VM_R90M  [C_B2]  36.87 47.3 0 bottom
PC1119  100U_D2_20VM_R55M  [C_D2]  36.86 54.3 90 bottom
PC1200  47U_0603_6.3V6M  [C_0603]  90.21 65.23 270 bottom
PC1201  47U_0603_6.3V6M  [C_0603]  91.73 65.23 270 bottom
PC1202  47U_0603_6.3V6M  [C_0603]  87.16 65.23 270 bottom
PC1203  47U_0603_6.3V6M  [C_0603]  88.68 65.23 270 bottom
PC1204  47U_0603_6.3V6M  [C_0603]  93.26 65.23 270 bottom
PC1205  47U_0603_6.3V6M  [C_0603]  94.78 65.23 270 bottom
PC1206  47U_0603_6.3V6M  [C_0603]  96.3 65.23 270 bottom
PC1214  22U_0603_6.3VAM  [C_0603]  86.1 48.7 270 top
PC1215  22U_0603_6.3VAM  [C_0603]  87.32 48.7 270 top
PC1216  22U_0603_6.3V6M  [C_0603]  88.52 48.7 270 top
PC1217  22U_0603_6.3V6M  [C_0603]  89.72 48.71 270 top
PC1218  22U_0603_6.3VAM  [C_0603]  86.12 42.48 90 top
PC1219  22U_0603_6.3VAM  [C_0603]  85.99 45.6 0 top
PC1220  22U_0603_6.3V6M  [C_0603]  89.88 45.57 180 top
PC1221  22U_0603_6.3VAM  [C_0603]  87.32 42.49 90 top
PC1222  22U_0603_6.3V6M  [C_0603]  88.53 42.5 90 top
PC1223  22U_0603_6.3V6M  [C_0603]  89.75 42.5 90 top
PC1224  22U_0603_6.3V6M  [C_0603]  100.34 65.12 0 top
PC1232  22U_0603_6.3V6M  [C_0603]  77.68 45.67 180 top
PC1233  22U_0603_6.3V6M  [C_0603]  77.68 46.89 180 top
PC1234  22U_0603_6.3V6M  [C_0603]  77.68 48.09 180 top
PC1235  22U_0603_6.3V6M  [C_0603]  77.68 44.46 180 top
PC1236  22U_0603_6.3VAM  [C_0603]  81.16 48.14 180 top
PC1237  330_B2_2.5VM_R9M  [C_B2]  99.16 67.2 180 bottom
PC1238  330_B2_2.5VM_R9M  [C_B2]  92.91 67.09 270 bottom
PC1239  330_B2_2.5VM_R9M  [C_B2]  96.12 67.08 270 bottom
PC1240  330_B2_2.5VM_R9M  [C_B2]  89.69 67.09 270 bottom
PC1241  330_B2_2.5VM_R9M  [C_B2]  86.37 67.58 0 bottom
PC1242  1U_0201_6.3V6M  [C_0201]  91.31 49.93 0 top
PC1243  1U_0201_6.3V6M  [C_0201]  89.58 52.6 0 top
PC1244  1U_0201_6.3V6M  [C_0201]  88.34 50.58 180 top
PC1245  1U_0201_6.3V6M  [C_0201]  86.52 50.57 0 top
PC1246  1U_0201_6.3V6M  [C_0201]  85.52 50.5 180 top
PC1247  1U_0201_6.3V6M  [C_0201]  83.76 50.3 90 top
PC1248  1U_0201_6.3V6M  [C_0201]  82.75 50.3 90 top
PC1249  1U_0201_6.3V6M  [C_0201]  81.81 50.3 90 top
PC1250  1U_0201_6.3V6M  [C_0201]  79.98 50.3 90 top
PC1251  1U_0201_6.3V6M  [C_0201]  79.04 50.3 90 top
PC1252  1U_0201_6.3V6M  [C_0201]  76.99 50.67 90 top
PC1253  1U_0201_6.3V6M  [C_0201]  76.4 50.67 90 top
PC1254  1U_0201_6.3V6M  [C_0201]  91.92 53.26 0 top
PC1255  1U_0201_6.3V6M  [C_0201]  89.58 53.23 0 top
PC1256  1U_0201_6.3V6M  [C_0201]  87.4 53.31 0 top
PC1257  1U_0201_6.3V6M  [C_0201]  82.1 53.23 0 top
PC1258  1U_0201_6.3V6M  [C_0201]  80.71 53.23 0 top
PC1259  1U_0201_6.3V6M  [C_0201]  79.31 53.23 0 top
PC1260  1U_0201_6.3V6M  [C_0201]  75.09 53.27 270 top
PC1261  1U_0201_6.3V6M  [C_0201]  74.52 53.23 270 top
PC1262  1U_0201_6.3VAM  [C_0201]  85.81 46.54 0 top
PC1263  1U_0201_6.3V6M  [C_0201]  90.03 46.51 180 top
PC1264  1U_0201_6.3VAM  [C_0201]  85.81 44.68 0 top
PC1265  1U_0201_6.3V6M  [C_0201]  90.05 44.66 180 top
PC1266  1U_0201_6.3V6M  [C_0201]  91.3 48.8 0 top
PC1267  1U_0201_6.3V6M  [C_0201]  91.3 48.24 0 top
PC1268  1U_0201_6.3V6M  [C_0201]  91.3 47.68 0 top
PC1269  1U_0201_6.3V6M  [C_0201]  91.3 47.12 0 top
PC1270  1U_0201_6.3V6M  [C_0201]  91.3 46.56 0 top
PC1271  1U_0201_6.3V6M  [C_0201]  91.3 46 0 top
PC1272  1U_0201_6.3V6M  [C_0201]  91.3 45.44 0 top
PC1273  1U_0201_6.3V6M  [C_0201]  91.3 44.88 0 top
PC1274  1U_0201_6.3V6M  [C_0201]  91.3 44.32 0 top
PC1275  1U_0201_6.3V6M  [C_0201]  91.3 43.76 0 top
PC1276  1U_0201_6.3V6M  [C_0201]  91.3 43.21 0 top
PC1277  22U_0603_6.3VAM  [C_0603]  81.16 46.94 180 top
PC1278  22U_0603_6.3VAM  [C_0603]  81.16 45.7 180 top
PC1279  22U_0603_6.3VAM  [C_0603]  81.19 44.45 180 top
PC1280  22U_0603_6.3VAM  [C_0603]  84.54 48.6 180 top
PC1281  22U_0603_6.3VAM  [C_0603]  84.54 47.39 180 top
PC1282  22U_0603_6.3VAM  [C_0603]  84.54 46.18 180 top
PC1283  22U_0603_6.3VAM  [C_0603]  84.54 44.98 180 top
PC1284  22U_0603_6.3VAM  [C_0603]  84.54 43.77 180 top
PC1285  22U_0603_6.3VAM  [C_0603]  84.54 42.56 180 top
PC1286  1U_0201_6.3V6M  [C_0201]  91.3 42.63 0 top
PC1287  1U_0201_6.3V6M  [C_0201]  91.3 42.06 0 top
PC1288  1U_0201_6.3V6M  [C_0201]  87.4 52.67 0 top
PC1289  1U_0201_6.3V6M  [C_0201]  90.75 51.73 0 top
PC1290  1U_0201_6.3V6M  [C_0201]  89.23 51.81 0 top
PC1291  1U_0201_6.3V6M  [C_0201]  87.65 51.68 180 top
PC1292  1U_0201_6.3V6M  [C_0201]  85.22 52.65 0 top
PC1293  1U_0201_6.3V6M  [C_0201]  85.22 53.28 0 top
PC1294  1U_0201_6.3V6M  [C_0201]  89.47 50.48 0 top
PC1295  1U_0201_6.3V6M  [C_0201]  87.95 39.83 180 top
PC1296  1U_0201_6.3V6M  [C_0201]  85.47 39.82 180 top
PC1297  1U_0201_6.3V6M  [C_0201]  86.05 39.82 0 top
PC1298  1U_0201_6.3V6M  [C_0201]  85.47 40.39 180 top
PC1299  1U_0201_6.3V6M  [C_0201]  87.96 40.39 180 top
PC1300  1U_0201_6.3V6M  [C_0201]  88.89 40.37 0 top
PC1301  1U_0201_6.3V6M  [C_0201]  91.22 40.37 0 top
PC1302  1U_0201_6.3V6M  [C_0201]  91.22 39.81 0 top
PC1303  1U_0201_6.3V6M  [C_0201]  88.89 39.81 0 top
PC1304  1U_0201_6.3V6M  [C_0201]  90.64 39.81 180 top
PC1305  47U_0603_6.3V6M  [C_0603]  55.74 49.11 90 bottom
PC1306  47U_0603_6.3V6M  [C_0603]  56.98 49.11 90 bottom
PC1307  47U_0603_6.3V6M  [C_0603]  58.28 49.09 90 bottom
PC1308  47U_0603_6.3V6M  [C_0603]  59.52 49.07 90 bottom
PC1309  47U_0603_6.3V6M  [C_0603]  60.79 49.09 90 bottom
PC1310  47U_0603_6.3V6M  [C_0603]  62.06 49.09 90 bottom
PC1311  47U_0603_6.3V6M  [C_0603]  55.98 42.45 270 bottom
PC1312  47U_0603_6.3V6M  [C_0603]  57.23 42.44 270 bottom
PC1313  47U_0603_6.3V6M  [C_0603]  58.55 42.45 270 bottom
PC1314  47U_0603_6.3V6M  [C_0603]  59.85 42.45 270 bottom
PC1315  47U_0603_6.3V6M  [C_0603]  61.14 42.45 270 bottom
PC1316  47U_0603_6.3V6M  [C_0603]  62.39 42.45 270 bottom
PC1323  22U_0603_6.3V6M  [C_0603]  67.83 52.66 270 top
PC1324  22U_0603_6.3V6M  [C_0603]  69.76 53.07 270 top
PC1325  22U_0603_6.3V6M  [C_0603]  66.14 48.28 90 top
PC1326  22U_0603_6.3V6M  [C_0603]  67.94 48.3 90 top
PC1327  22U_0603_6.3V6M  [C_0603]  64.49 48.28 90 top
PC1328  22U_0603_6.3V6M  [C_0603]  66.12 45.56 90 top
PC1329  22U_0603_6.3V6M  [C_0603]  67.94 45.56 90 top
PC1330  22U_0603_6.3V6M  [C_0603]  64.49 45.54 90 top
PC1331  22U_0603_6.3V6M  [C_0603]  65.68 43.58 270 top
PC1332  22U_0603_6.3V6M  [C_0603]  66.95 43.58 270 top
PC1333  22U_0603_6.3V6M  [C_0603]  64.49 43.58 270 top
PC1334  22U_0603_6.3V6M  [C_0603]  68.27 43.58 270 top
PC1335  22U_0603_6.3V6M  [C_0603]  74.59 50.06 90 top
PC1336  22U_0603_6.3V6M  [C_0603]  72.81 53.14 270 top
PC1337  22U_0603_6.3V6M  [C_0603]  71.41 48.09 0 top
PC1338  22U_0603_6.3V6M  [C_0603]  71.38 46.89 0 top
PC1339  22U_0603_6.3V6M  [C_0603]  71.38 45.7 0 top
PC1340  22U_0603_6.3V6M  [C_0603]  71.38 44.51 0 top
PC1341  22U_0603_6.3V6M  [C_0603]  71.38 43.31 0 top
PC1342  22U_0603_6.3V6M  [C_0603]  71.38 42.12 0 top
PC1343  22U_0603_6.3V6M  [C_0603]  73.87 48.09 0 top
PC1344  22U_0603_6.3V6M  [C_0603]  73.87 46.89 0 top
PC1345  22U_0603_6.3V6M  [C_0603]  73.87 45.7 0 top
PC1346  22U_0603_6.3V6M  [C_0603]  73.9 44.51 0 top
PC1347  22U_0603_6.3V6M  [C_0603]  73.9 43.31 0 top
PC1348  22U_0603_6.3V6M  [C_0603]  73.9 42.12 0 top
PC1349  330_B2_2.5VM_R9M  [C_B2]  51.11 52.11 0 bottom
PC1350  330_B2_2.5VM_R9M  [C_B2]  52.29 41.66 0 bottom
PC1351  1U_0201_6.3V6M  [C_0201]  73.38 50.27 90 top
PC1352  1U_0201_6.3V6M  [C_0201]  72.47 50.26 90 top
PC1353  1U_0201_6.3V6M  [C_0201]  71.53 50.26 90 top
PC1354  1U_0201_6.3V6M  [C_0201]  70.61 50.26 90 top
PC1355  1U_0201_6.3V6M  [C_0201]  69.53 50.76 180 top
PC1356  1U_0201_6.3V6M  [C_0201]  68.91 49.19 90 top
PC1357  1U_0201_6.3V6M  [C_0201]  69.59 49.17 90 top
PC1358  1U_0201_6.3V6M  [C_0201]  69.47 47.36 90 top
PC1359  1U_0201_6.3V6M  [C_0201]  68.83 47.36 90 top
PC1360  1U_0201_6.3V6M  [C_0201]  69.47 45.71 90 top
PC1361  1U_0201_6.3V6M  [C_0201]  68.88 45.71 90 top
PC1362  1U_0201_6.3V6M  [C_0201]  69.44 44.21 270 top
PC1363  1U_0201_6.3V6M  [C_0201]  66.03 51.69 180 top
PC1364  1U_0201_6.3V6M  [C_0201]  66 50.91 180 top
PC1365  22U_0603_6.3V6M  [C_0603]  124.7 54.1 270 top
PC1366  22U_0603_6.3V6M  [C_0603]  123.5 54.1 270 top
PC1367  22U_0603_6.3VAM  [C_0603]  129.49 55.74 270 bottom
PC1368  22U_0603_6.3VAM  [C_0603]  128.29 55.74 270 bottom
PC1369  22U_0603_6.3VAM  [C_0603]  127.09 55.73 270 bottom
PC1370  22U_0603_6.3VAM  [C_0603]  130.72 55.74 270 bottom
PC1371  22U_0603_6.3V6M  [C_0603]  94.19 48.47 180 top
PC1372  22U_0603_6.3V6M  [C_0603]  94.19 47.27 180 top
PC1373  22U_0603_6.3V6M  [C_0603]  94.26 46.08 180 top
PC1374  22U_0603_6.3V6M  [C_0603]  94.22 42.5 180 top
PC1375  22U_0603_6.3V6M  [C_0603]  94.23 43.69 180 top
PC1376  22U_0603_6.3V6M  [C_0603]  94.23 44.89 180 top
PC1377  1U_0201_6.3V6M  [C_0201]  93.17 49.93 180 top
PC1378  1U_0201_6.3V6M  [C_0201]  94.97 47.44 0 top
PC1379  1U_0201_6.3V6M  [C_0201]  94.97 48.01 0 top
PC1380  1U_0201_6.3V6M  [C_0201]  94.97 48.58 0 top
PC1381  1U_0201_6.3V6M  [C_0201]  93.55 41.55 180 top
PC1382  1U_0201_6.3V6M  [C_0201]  94.18 39.83 180 top
PC1383  1U_0201_6.3V6M  [C_0201]  94.18 40.47 180 top
PC1401  10U_0603_25V6M  [C_0603]  103.52 15.07 180 bottom
PC1402  10U_0603_25V6M  [C_0603]  103.53 16.27 180 bottom
PC1403  22U_0603_6.3V6M  [C_0603]  105.8 24.74 0 bottom
PC1404  22U_0603_6.3V6M  [C_0603]  105.8 23.54 0 bottom
PC1405  22U_0603_6.3V6M  [C_0603]  105.81 25.95 0 bottom
PC1406  0.1U_0402_25V6  [C_0402]  104.48 15.73 270 bottom
PC1407  2200P_0402_50V7K  [C_0402]  105.35 16.41 0 bottom
PC1408  680P_0402_50V7K  [C_0402]  101.69 24.6 180 bottom
PC1409  1U_0402_16VAK  [C_0402]  107.04 20.69 270 bottom
PC1410  0.22U_0402_25V6K  [C_0402]  123.48 48.6 90 bottom
PC1411  680P_0402_50V7K  [C_0402]  120.17 48.62 180 bottom
PC1412  0.1U_0402_25V6  [C_0402]  129.99 48.3 90 bottom
PC1413  2200P_0402_50V7K  [C_0402]  128.96 48.29 90 bottom
PC1414  10U_0603_25V6M  [C_0603]  130.34 47.33 270 bottom
PC1415  10U_0603_25V6M  [C_0603]  129.12 47.34 270 bottom
PC1416  22U_0603_6.3V6M  [C_0603]  120.75 43.18 270 bottom
PC1417  22U_0603_6.3V6M  [C_0603]  119.54 43.18 270 bottom
PC1418  22U_0603_6.3V6M  [C_0603]  121.97 43.18 270 bottom
PC1419  1U_0402_16VAK  [C_0402]  125.3 50.37 0 bottom
PC1420  0.22U_0402_25V6K  [C_0402]  105.76 22.5 0 bottom
PC1421  10U_0603_16VAM  [C_0603]  115.29 72.47 90 bottom
PC1422  10U_0603_16VAM  [C_0603]  114.02 71.46 270 bottom
PC1423  100P_0402_50V8J  [C_0402]  124.81 70.19 270 bottom
PC1424  100P_0402_50V8J  [C_0402]  123.91 70.19 270 bottom
PC1425  0.1U_0402_25V6  [C_0402]  17.26 75.02 90 top
PC1426  0.1U_0402_25V6  [C_0402]  12.22 55.57 90 top
PC1500  0.01U_0402_50V7K  [C_0402]  36.93 35.36 270 top
PC1501  0.01U_0402_50V7K  [C_0402]  82.16 72.61 90 top
PC1502  100P_0402_50V8J  [C_0402]  86.66 74.12 180 top
PC1503  100P_0402_50V8J  [C_0402]  80.94 75.71 180 top
PC1504  100P_0402_50V8J  [C_0402]  40.31 31.43 270 top
PC1505  0.22U_0402_25V6K  [C_0402]  39.33 27.41 0 top
PCB46  0.1U_0402_25V6  [C_0402]  31.69 39.2 270 top
PD102  -  [RB520SM-30T2R_EMD2-2]  18.62 41.62 180 top
PD103  -  [RB520SM-30T2R_EMD2-2]  24.65 44.68 0 top
PD104  -  [TVNST52302AB0_SOT523-3]  41.09 22.22 0 top
PD105  -  [TVNST52302AB0_SOT523-3]  40.54 15.9 180 top
PD200  -  [SMF4L22A_SOD123FL2]  26.63 42.63 180 bottom
PD201  -  [RB520SM-30T2R_EMD2-2]  22.16 22.73 90 top
PD202  -  [RB520SM-30T2R_EMD2-2]  20.95 22.73 90 top
PD1500  -  [RB520SM-30T2R_EMD2-2]  38.34 35.02 0 top
PD1501  -  [RB520SM-30T2R_EMD2-2]  38.32 36.26 0 top
PD1502  -  [RB520SM-30T2R_EMD2-2]  37.89 30.65 180 top
PD1503  -  [RB520SM-30T2R_EMD2-2]  84.73 75.27 180 top
PD1504  -  [RB520SM-30T2R_EMD2-2]  131 39.11 180 bottom
PD1505  -  [RB520SM-30T2R_EMD2-2]  131 37.87 180 bottom
PDB4  -  [RB520SM-30T2R_EMD2-2]  27.2 38.18 180 top
PDB5  -  [RB520SM-30T2R_EMD2-2]  27.2 36.94 180 top
PJP300  PAD-OPEN 4X4M  [JUMP_43X118]  192.44 38.6 270 bottom
PJP400  PAD-OPEN 4X4M  [JUMP_43X118]  30.33 42.53 180 bottom
PJP401  PAD-OPEN 4X4M  [JUMP_43X118]  292.73 68.53 90 bottom
PJP500  PAD-OPEN 4X4M  [JUMP_43X118]  115.03 31.02 90 bottom
PJP600  -  [JUMP_43X118]  53.23 19.28 0 bottom
PJP601  -  [JUMP_43X39]  52.36 26.73 0 bottom
PJP800  -  [JUMP_43X79]  118.44 60.42 180 bottom
PJP1400  -  [JUMP_43X79]  103.39 26.27 90 bottom
PJP1401  -  [JUMP_43X79]  120.26 46.18 180 bottom
PL100  HCB2012KF-800T50_2P  [TAI-T_HCB2012KF-121T50_2P]  9.31 65.77 270 bottom
PL101  HCB2012KF-800T50_2P  [TAI-T_HCB2012KF-121T50_2P]  9.22 51.89 270 bottom
PL102  HCB2012KF-800T50_2P  [TAI-T_HCB2012KF-121T50_2P]  45.35 16.64 270 bottom
PL103  HCB2012KF-800T50_2P  [TAI-T_HCB2012KF-121T50_2P]  43.81 16.44 180 bottom
PL104  HCB2012KF-800T50_2P  [TAI-T_HCB2012KF-121T50_2P]  43.81 18.28 180 bottom
PL200  1UH_MLV-FY12N1R0M-C1L_4.9A_20%  [MAG_MLV-FY12N1R0M-C1L_2P]  26.17 40.09 180 bottom
PL201  1.5UH_MMD-10BDE1R5M-R1L_24A_20%  [MAG_MMD-10BDE1R5M-R1L_2P]  24.21 33.41 0 bottom
PL300  HCB2012KF-800T50_2P  [TAI-T_HCB2012KF-121T50_2P]  201.03 35.1 90 bottom
PL301  1.5UH_MMD-06CZ-1R5M-V1_9A_20%  [MAG_MMD-06CZ-1R5M-V1_2P]  199.27 50.99 180 bottom
PL302  HCB2012KF-800T50_2P  [TAI-T_HCB2012KF-121T50_2P]  202.87 35.1 90 bottom
PL400  HCB2012KF-800T50_2P  [TAI-T_HCB2012KF-121T50_2P]  47.23 38.98 90 bottom
PL401  1.5UH_MMD-05AHN1R5M-M1L_6.2A_20%  [MAG_MMD-05AHN1R5M-M1L_2P]  36.97 39.43 90 bottom
PL402  HCB2012KF-800T50_2P  [TAI-T_HCB2012KF-121T50_2P]  295.5 55.39 0 bottom
PL403  1.5UH_MMD-05AHN1R5M-M1L_6.2A_20%  [MAG_MMD-05AHN1R5M-M1L_2P]  298.64 64.42 180 bottom
PL404  HCB2012KF-800T50_2P  [TAI-T_HCB2012KF-121T50_2P]  45.44 38.98 90 bottom
PL405  HCB2012KF-800T50_2P  [TAI-T_HCB2012KF-121T50_2P]  295.5 53.61 0 bottom
PL500  1UH_PCMB042T-1R0MS_4.5A_20%  [CYNTE_PCMB042T-1R0MS_2P]  110.24 22.98 90 bottom
PL501  HCB2012KF-800T50_2P  [TAI-T_HCB2012KF-121T50_2P]  118.45 26.07 270 bottom
PL600  HCB2012KF-800T50_2P  [TAI-T_HCB2012KF-121T50_2P]  46.38 30.93 0 bottom
PL601  1UH_MHCI05015B-1R0M-R8A_6.5A_20%  [CHILI_MHCI05015B-1R0M-R8A_2P]  49.09 20.65 270 bottom
PL800  HCB2012KF-800T50_2P  [TAI-T_HCB2012KF-121T50_2P]  128.9 52.7 180 bottom
PL801  1UH_PCMB041B-1R0MS_4.2A_20%  [CYNTE_PCMB041B-1R0MS_2P]  123.09 57.46 90 bottom
PL1000  0.15UH_MHCB06024-R15M-C1R885_27A_20%  [CHILI_MHCB06024-R15M-C1R885_2P]  79.59 72.76 0 bottom
PL1001  HCB2012KF-800T50_2P  [TAI-T_HCB2012KF-121T50_2P]  71.23 75.62 270 bottom
PL1002  HCB2012KF-800T50_2P  [TAI-T_HCB2012KF-121T50_2P]  69.4 75.62 270 bottom
PL1003  HCB2012KF-800T50_2P  [TAI-T_HCB2012KF-121T50_2P]  123.36 75.81 270 bottom
PL1004  0.15UH_MHCB06024-R15M-C1R885_27A_20%  [CHILI_MHCB06024-R15M-C1R885_2P]  106.14 72.84 180 bottom
PL1005  HCB2012KF-800T50_2P  [TAI-T_HCB2012KF-121T50_2P]  125.33 75.81 270 bottom
PL1100  0.15UH_MHCB06024-R15M-C1R885_27A_20%  [CHILI_MHCB06024-R15M-C1R885_2P]  47.13 46.89 0 bottom
PL1101  HCB2012KF-800T50_2P  [TAI-T_HCB2012KF-121T50_2P]  130.75 72.83 270 bottom
PL1102  0.47UH_CMME051B-R47MS_8A_20%  [CYNTE_CMME051B-R47MS_2P]  128.67 62.03 270 bottom
PL1103  HCB2012KF-800T50_2P  [TAI-T_HCB2012KF-121T50_2P]  33.52 54.63 90 bottom
PL1104  HCB2012KF-800T50_2P  [TAI-T_HCB2012KF-121T50_2P]  33.51 59.25 270 bottom
PL1400  HCB1608KF-121T30_0603  [CHILI_PBY160808T-300Y-N_2P]  106.73 14.98 180 bottom
PL1401  0.68UH_HEI322512B-R68M-Q8_4.4A_20%  [CHILI_HEI322512B-R68M-Q8_2P]  103.69 21.47 90 bottom
PL1402  HCB1608KF-121T30_0603  [CHILI_PBY160808T-300Y-N_2P]  131.16 50.11 270 bottom
PL1403  0.68UH_HEI322512B-R68M-Q8_4.4A_20%  [CHILI_HEI322512B-R68M-Q8_2P]  123.06 47.35 270 bottom
PQ100  -  [AON7405_DFN8-5]  11.46 62.72 0 bottom
PQ101  -  [AON7405_DFN8-5]  13.12 57.98 270 bottom
PQ102  S TR AO7401 1P SC70-3  [SI1303DL-T1-E3_SOT323-3]  12.69 65.35 270 top
PQ103  S TR AO7401 1P SC70-3  [SI1303DL-T1-E3_SOT323-3]  12.69 62.6 270 top
PQ104  -  [DMN66D0LDW-7_SOT363-6]  37.05 65.16 0 top
PQ105  -  [DMN66D0LDW-7_SOT363-6]  17.94 67.27 90 top
PQ106  -  [DMN66D0LDW-7_SOT363-6]  36.33 63.91 180 top
PQ107  -  [L2N7002WT1G_SC70-3]  12.53 59.98 270 top
PQ108  -  [L2N7002WT1G_SC70-3]  13.98 71.49 0 top
PQ109  -  [DMN66D0LDW-7_SOT363-6]  17.49 64.98 180 top
PQ110  -  [L2N7002WT1G_SC70-3]  16.46 73.95 180 top
PQ111  -  [L2N7002WT1G_SC70-3]  14.77 69.61 90 top
PQ112  -  [DMN66D0LDW-7_SOT363-6]  40.55 64.15 180 top
PQ113  -  [DMN66D0LDW-7_SOT363-6]  40.78 67.86 180 top
PQ114  -  [DMN66D0LDW-7_SOT363-6]  35.03 58.95 0 top
PQ115  -  [AON7405_DFN8-5]  11.52 49.9 0 bottom
PQ116  -  [AON7405_DFN8-5]  10.54 43.33 90 bottom
PQ117  S TR AO7401 1P SC70-3  [SI1303DL-T1-E3_SOT323-3]  12.69 50.88 270 top
PQ118  S TR AO7401 1P SC70-3  [SI1303DL-T1-E3_SOT323-3]  14.71 42.91 90 top
PQ119  -  [DMN66D0LDW-7_SOT363-6]  12.8 48.66 270 top
PQ120  -  [L2N7002WT1G_SC70-3]  12.29 45.55 270 top
PQ122  -  [L2N7002WT1G_SC70-3]  12.53 54.26 270 top
PQ123  -  [DMN66D0LDW-7_SOT363-6]  9.24 45.48 270 top
PQ124  -  [L2N7002WT1G_SC70-3]  12.53 57.5 270 top
PQ126  -  [L2N7002WT1G_SC70-3]  10.29 49.35 180 top
PQ129  -  [L2N7002WT1G_SC70-3]  23.07 40.94 270 top
PQ130  -  [L2N7002WT1G_SC70-3]  28.08 46.62 180 top
PQ201  -  [AON6962_DFN5X6D-8-7]  16.99 35.39 0 bottom
PQ202  -  [AON7405_DFN8-5]  42.39 23.03 0 bottom
PQ203  -  [AON6962_DFN5X6D-8-7]  36.89 36.19 0 bottom
PQ205  -  [L2N7002WT1G_SC70-3]  22.26 11.83 270 top
PQ700  -  [L2N7002WT1G_SC70-3]  127.49 38.49 180 bottom
PQ1500  -  [L2N7002WT1G_SC70-3]  21.6 7.6 90 top
PQ1501  -  [L2N7002WT1G_SC70-3]  27.62 54.94 0 top
PQ1502  -  [L2N7002WT1G_SC70-3]  20.51 65.21 270 top
PQ1506  S TR AO7401 1P SC70-3  [SI1303DL-T1-E3_SOT323-3]  130.09 35.35 0 bottom
PQ1507  -  [L2N7002WT1G_SC70-3]  35.22 34.86 0 top
PR100  300K_0201_1%  [R_0201]  15.34 66.43 270 top
PR101  300K_0201_1%  [R_0201]  15.34 63.68 270 top
PR102  200K_0201_5%  [R_0201]  36.13 68.46 270 top
PR103  1M_0402_1%  [R_0402]  9.38 59.45 180 bottom
PR104  499K_0402_1%  [R_0402]  14.27 67.1 180 top
PR105  499K_0402_1%  [R_0402]  10.64 63.33 270 top
PR106  0_0402_5%  [R0402_0OHM]  36.08 67.19 270 top
PR107  200K_0201_5%  [R_0201]  37.84 62.58 180 top
PR108  0_0402_5%  [R0402_0OHM]  33.11 63.52 90 top
PR109  0_0402_5%  [R0402_0OHM]  37.3 63.33 90 top
PR110  330K_0201_1%  [R_0201]  15.9 65.79 90 top
PR111  0_0402_5%  [R0402_0OHM]  37.72 67.96 180 top
PR112  49.9K_0402_1%  [R_0402]  11.45 61.64 270 top
PR113  330K_0201_1%  [R_0201]  15.34 62.51 270 top
PR114  0_0402_5%  [R0402_0OHM]  38.12 64.24 270 top
PR115  49.9K_0402_1%  [R_0402]  12.6 67.1 90 top
PR116  200K_0201_5%  [R_0201]  17.18 69.42 0 top
PR117  0_0402_5%  [R0402_0OHM]  35.1 65.04 0 top
PR118  0_0402_5%  [R0402_0OHM]  15.44 60.36 90 top
PR119  200K_0201_5%  [R_0201]  15.34 64.68 90 top
PR120  0_0402_5%  [R0402_0OHM]  18.01 66.22 180 top
PR121  1M_0201_1%  [R_0201]  15.34 59.13 90 top
PR122  200K_0201_5%  [R_0201]  16.55 69.49 180 top
PR123  1M_0201_1%  [R_0201]  16.46 66.38 270 top
PR124  1M_0201_1%  [R_0201]  14.96 70.5 90 top
PR125  0_0402_5%  [R0402_0OHM]  15.14 68.01 270 top
PR126  0_0402_5%  [R0402_0OHM]  17.32 70.15 90 top
PR127  0_0402_5%  [R0402_0OHM]  19.43 63.02 180 top
PR128  200K_0201_5%  [R_0201]  16.66 70.08 90 top
PR129  0_0402_5%  [R0402_0OHM]  38.2 60.92 180 top
PR130  0_0402_5%  [R0402_0OHM]  34.06 64.43 270 top
PR131  0_0402_5%  [R0402_0OHM]  12.36 72.12 270 top
PR132  1M_0201_1%  [R_0201]  18.43 64.6 90 top
PR133  0_0402_5%  [R0402_0OHM]  16 70.15 90 top
PR134  0_0402_5%  [R0402_0OHM]  41.5 62.81 90 top
PR135  0_0402_5%  [R0402_0OHM]  33.12 62.57 0 top
PR136  200K_0201_5%  [R_0201]  43.15 65.04 180 top
PR137  200K_0201_5%  [R_0201]  33.37 60.53 90 top
PR138  200K_0201_5%  [R_0201]  38.53 68.47 270 top
PR139  200K_0201_5%  [R_0201]  38.2 58.82 180 top
PR140  0_0402_5%  [R0402_0OHM]  39.28 65.04 0 top
PR141  0_0402_5%  [R0402_0OHM]  34.07 58.44 90 top
PR142  0_0402_5%  [R_0402]  40.93 65.04 0 top
PR143  0_0402_5%  [R_0402]  34.06 60.15 90 top
PR144  300K_0201_1%  [R_0201]  12.05 42.24 90 top
PR145  1M_0402_1%  [R_0402]  14.71 52.64 180 top
PR146  300K_0201_1%  [R_0201]  15.34 51.96 270 top
PR147  499K_0402_1%  [R_0402]  10.64 51.36 270 top
PR148  499K_0402_1%  [R_0402]  13.4 41.11 0 top
PR149  330K_0201_1%  [R_0201]  15.34 50.79 270 top
PR150  49.9K_0402_1%  [R_0402]  10.24 46.43 0 top
PR151  330K_0201_1%  [R_0201]  12.05 43.41 90 top
PR152  49.9K_0402_1%  [R_0402]  12.17 52.64 0 top
PR153  200K_0201_5%  [R_0201]  11.98 47.01 90 top
PR154  0_0402_5%  [R0402_0OHM]  15.96 45.1 0 top
PR155  200K_0201_5%  [R_0201]  8.42 45.29 270 top
PR157  0_0402_5%  [R0402_0OHM]  15.59 47.39 90 top
PR158  1M_0201_1%  [R_0201]  15.21 44.3 90 top
PR160  200K_0201_5%  [R_0201]  15.34 55.75 270 top
PR161  1M_0201_1%  [R_0201]  15.53 48.97 90 top
PR163  1M_0201_1%  [R_0201]  15.34 54.59 270 top
PR165  0_0402_5%  [R0402_0OHM]  11.21 49.61 0 top
PR166  0_0402_5%  [R0402_0OHM]  15.44 58.49 270 top
PR167  0_0402_5%  [R0402_0OHM]  10.27 42.36 90 top
PR169  200K_0201_5%  [R_0201]  15.34 56.34 90 top
PR170  0_0402_5%  [R0402_0OHM]  8.67 47.17 90 top
PR172  1M_0201_1%  [R_0201]  9.57 43.33 180 top
PR174  0_0402_5%  [R0402_0OHM]  14.39 55.88 180 top
PR178  221K_0402_1%  [R_0402]  20.44 43.5 270 top
PR179  1M_0402_1%  [R_0402]  24.51 43.6 270 top
